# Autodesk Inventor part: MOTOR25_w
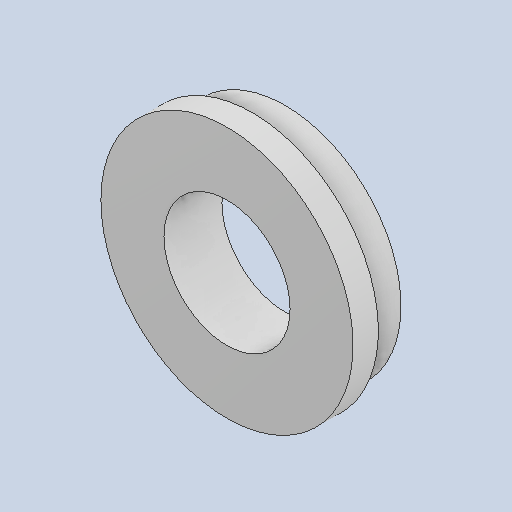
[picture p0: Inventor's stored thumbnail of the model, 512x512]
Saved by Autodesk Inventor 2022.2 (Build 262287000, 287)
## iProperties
Created: 2024-10
Part Number: MOTOR25_w
Material: Generico
Document SubType Name: Modeling
Designer: 18907419
Density: 1 g/cm^3
Appearance: Default
Author: 18907419
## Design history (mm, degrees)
feature "Solido1"
node "Solido2"
